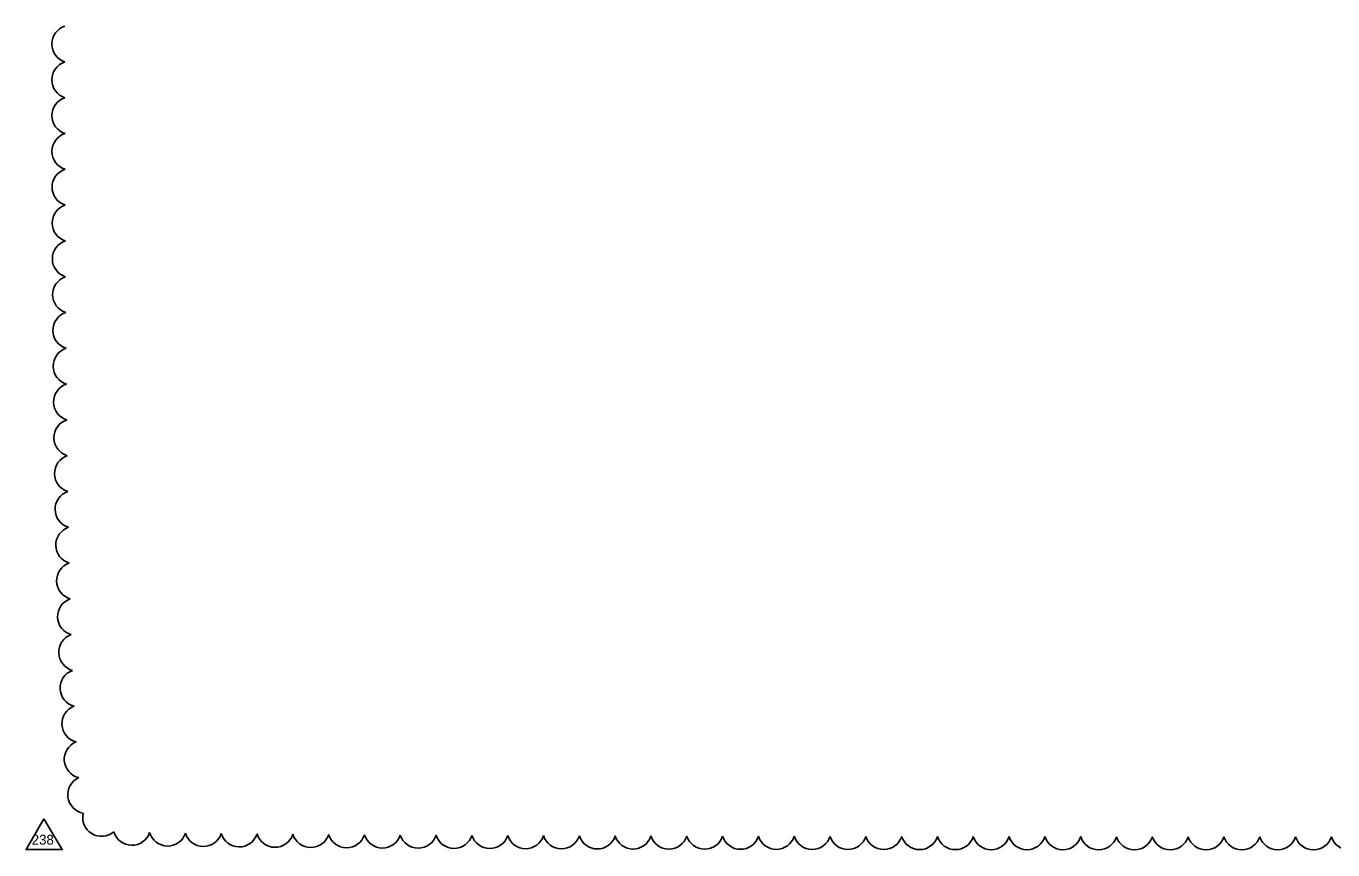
# Model space of a CAD drawing. Extents: x -811.2 to -795, y -2307.6 to -2235.1.
# Drawn here: x -811.23 to -803.27, y -2294.51 to -2289.48 of the extents above; entities that cross this region are included whole.
import ezdxf

# ---------------------------------------------------------------- set-up
doc = ezdxf.new("R2010")
doc.units = 0
doc.layers.add('Cloud_dp', color=7, linetype='Continuous')

msp = doc.modelspace()

# ---------------------------------------------------------------- linework, layer by layer
at = {"layer": 'Cloud_dp'}
msp.add_lwpolyline([(-811.1249, -2294.3178), (-811.2327, -2294.5059), (-811.012, -2294.5059)], close=True, dxfattribs=at)
for centre, radius, start, end in [((-810.9616, -2289.593), 0.1145, 107.49902, 252.49902), ((-810.9615, -2289.8114), 0.1145, 107.53555, 252.53555), ((-810.9613, -2290.0296), 0.1145, 107.5822, 252.5822), ((-810.9609, -2290.2479), 0.1145, 107.6325, 252.6325), ((-810.9602, -2290.4662), 0.1145, 107.68694, 252.68694), ((-810.9594, -2290.6845), 0.1145, 107.74613, 252.74613), ((-810.9584, -2290.9028), 0.1145, 107.8108, 252.8108), ((-810.957, -2291.1211), 0.1145, 107.88185, 252.88185), ((-810.9554, -2291.3393), 0.1145, 107.96041, 252.96041), ((-810.9535, -2291.5576), 0.1145, 108.04789, 253.04789), ((-810.9512, -2291.7759), 0.1145, 108.14614, 253.14614), ((-810.9486, -2291.9941), 0.1145, 108.25756, 253.25756), ((-810.9454, -2292.2123), 0.1145, 108.38536, 253.38536), ((-810.9418, -2292.4305), 0.1145, 108.53403, 253.53403), ((-810.9375, -2292.6487), 0.1145, 108.70992, 253.70992), ((-810.9325, -2292.8668), 0.1145, 108.92254, 253.92254), ((-810.9266, -2293.0849), 0.1145, 109.18674, 254.18674), ((-810.9195, -2293.3029), 0.1145, 109.52751, 254.52751), ((-810.9109, -2293.5208), 0.1145, 109.99095, 254.99095), ((-810.9001, -2293.7384), 0.1145, 110.67491, 255.67491), ((-810.8859, -2293.9556), 0.1145, 111.8417, 256.8417), ((-810.8642, -2294.1711), 0.1145, 114.67182, 259.67182), ((-810.7735, -2294.3109), 0.1144, 166.22993, 311.22993), ((-810.5881, -2294.3652), 0.1145, 196.10716, 341.10716), ((-810.3701, -2294.3696), 0.1145, 196.57377, 341.57377), ((-810.1519, -2294.3728), 0.1145, 196.78771, 341.78771), ((-809.9337, -2294.3752), 0.1145, 196.91793, 341.91793), ((-809.7155, -2294.3773), 0.1145, 197.00795, 342.00795), ((-809.4972, -2294.379), 0.1145, 197.075, 342.075), ((-809.2789, -2294.3805), 0.1145, 197.12743, 342.12743), ((-809.0606, -2294.3819), 0.1145, 197.16991, 342.16991), ((-808.8423, -2294.3831), 0.1145, 197.20522, 342.20522), ((-808.624, -2294.3841), 0.1145, 197.23518, 342.23518), ((-808.4057, -2294.3851), 0.1145, 197.26103, 342.26103), ((-808.1874, -2294.386), 0.1145, 197.28362, 342.28362), ((-807.9691, -2294.3867), 0.1145, 197.30358, 342.30358), ((-807.7508, -2294.3875), 0.1145, 197.32139, 342.32139), ((-807.5324, -2294.3881), 0.1145, 197.33741, 342.33741), ((-807.3141, -2294.3887), 0.1145, 197.35192, 342.35192), ((-807.0958, -2294.3892), 0.1145, 197.36514, 342.36514), ((-806.8775, -2294.3897), 0.1145, 197.37726, 342.37726), ((-806.6592, -2294.3902), 0.1145, 197.38842, 342.38842), ((-806.4409, -2294.3906), 0.1145, 197.39873, 342.39873), ((-806.2226, -2294.391), 0.1145, 197.40831, 342.40831), ((-806.0042, -2294.3913), 0.1145, 197.41723, 342.41723), ((-805.7859, -2294.3916), 0.1145, 197.42557, 342.42557), ((-805.5676, -2294.3919), 0.1145, 197.43338, 342.43338), ((-805.3493, -2294.3921), 0.1145, 197.44073, 342.44073), ((-805.131, -2294.3923), 0.1145, 197.44765, 342.44765), ((-804.9126, -2294.3925), 0.1145, 197.45418, 342.45418), ((-804.6943, -2294.3927), 0.1145, 197.46036, 342.46036), ((-804.476, -2294.3928), 0.1145, 197.46623, 342.46623), ((-804.2577, -2294.3929), 0.1145, 197.47179, 342.47179), ((-804.0394, -2294.393), 0.1145, 197.47709, 342.47709), ((-803.821, -2294.3931), 0.1145, 197.48214, 342.48214), ((-803.6027, -2294.3931), 0.1145, 197.48696, 342.48696), ((-803.3844, -2294.3932), 0.1145, 197.49157, 342.49157), ((-803.1661, -2294.3932), 0.1145, 197.49598, 342.49598)]:
    msp.add_arc(centre, radius, start, end, dxfattribs=at)

# ---------------------------------------------------------------- texts
msp.add_text('238', height=0.05998, rotation=0, dxfattribs=at).set_placement((-811.1979, -2294.4758))

doc.saveas('drawing.dxf')
